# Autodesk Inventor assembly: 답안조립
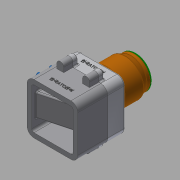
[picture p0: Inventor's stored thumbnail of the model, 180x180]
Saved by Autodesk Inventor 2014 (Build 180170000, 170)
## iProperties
Created: 2018-01
Part Number: 답안조립
Document SubType Name: Assembly
Designer: user
Author: user
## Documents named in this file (9)
- C:\Users\user\Desktop\480108V1007\답안조립.iam
- C:\Users\user\Desktop\480108V1007\본체.ipt
- C:\Users\user\Desktop\480108V1007\본체커버.ipt
- C:\Users\user\Desktop\480108V1007\볼트 M3x12.ipt
- C:\Users\user\Desktop\480108V1007\용기.ipt
- C:\Users\user\Desktop\480108V1007\용기캡.ipt
- C:\Users\user\Desktop\480108V1007\핸들.ipt
- C:\Users\user\Desktop\480108V1007\핸들축.ipt
- C:\Users\user\Desktop\480108V1007\볼트 M4x12.ipt
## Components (2 placed, 2 different names)
1. 핸들축:1
2. 핸들:1
